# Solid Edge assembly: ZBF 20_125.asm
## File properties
Title: Zylinder
Author: bmolnar
Template: iso metric assembly.asm
Last saved by: bmolnar
Revision: 21
Application: Solid Edge
Username: bmolnar
Dokumentum tartalom típus: 1
Document Number: ZBF 20/125
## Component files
Profilrohr.par
Kolbenstange.par
Kit.par
Mutter.par
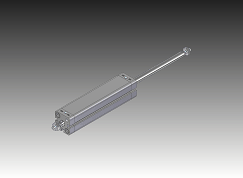
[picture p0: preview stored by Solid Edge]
